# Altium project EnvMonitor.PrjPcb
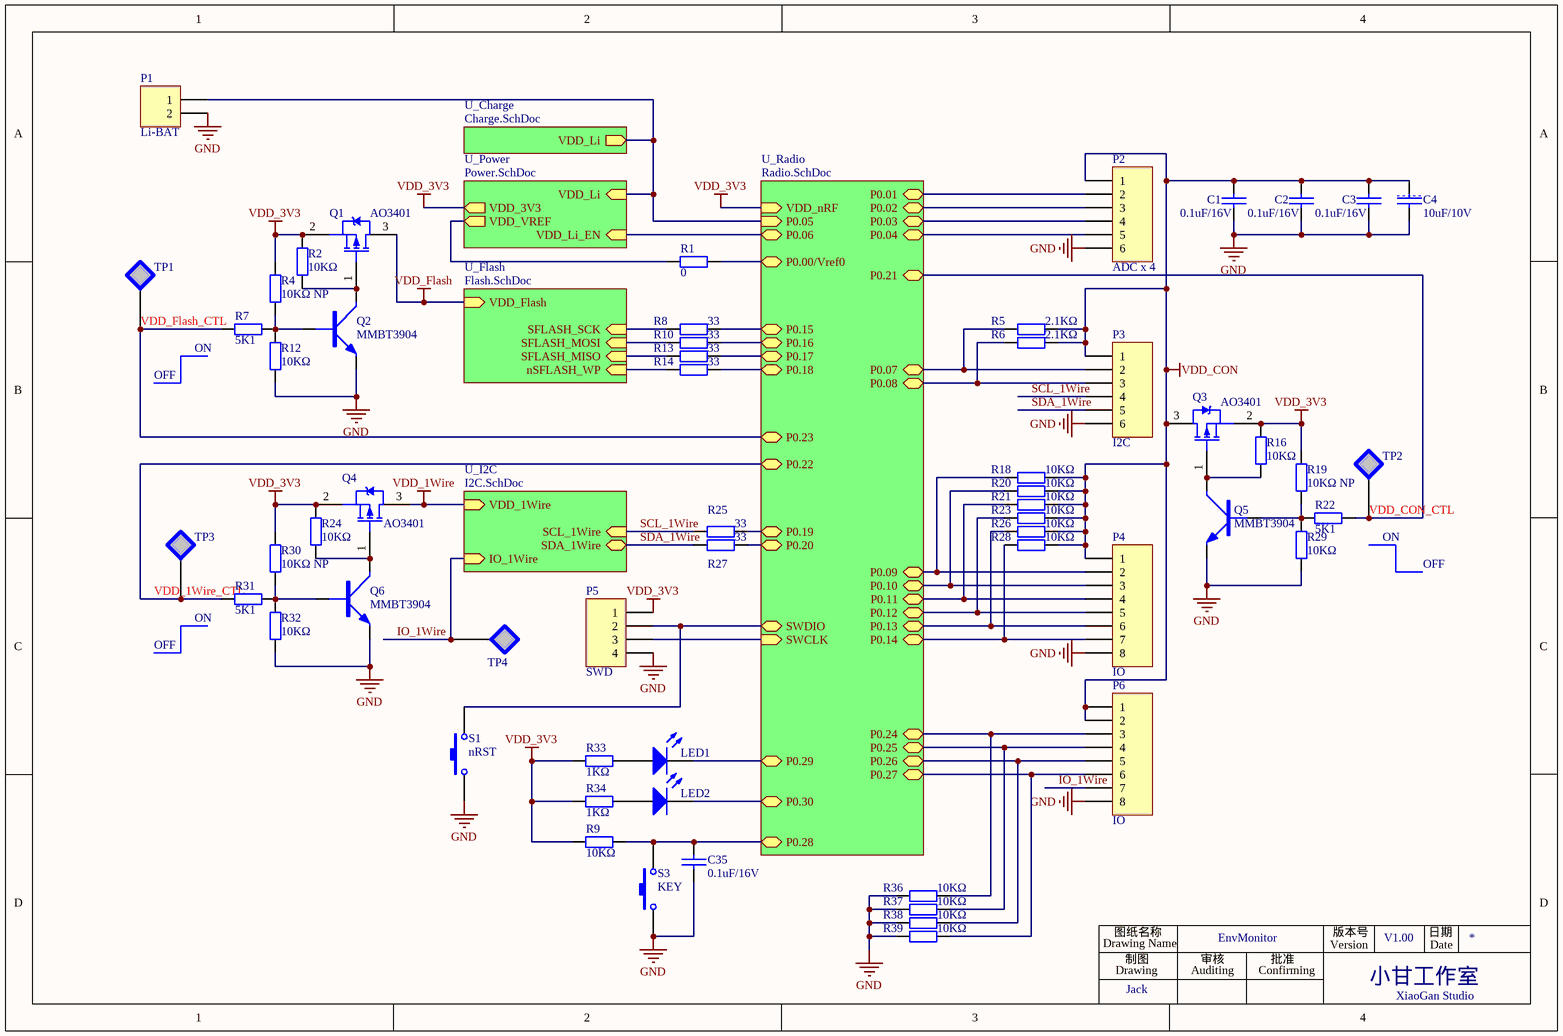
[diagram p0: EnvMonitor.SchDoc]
6 sheets, 146 parts. Net scope: hierarchical (ports join the sheet entries above them; power ports are global).
Sheets:
  EnvMonitor.SchDoc
    U_Radio = Radio.SchDoc
    U_Flash = Flash.SchDoc
    U_Power = Power.SchDoc
    U_I2C = I2C.SchDoc
    U_Charge = Charge.SchDoc

## Sheet EnvMonitor.SchDoc
size A4

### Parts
C1  0.1uF/16V  [0603]
C2  0.1uF/16V  [0603]
C3  0.1uF/16V  [0603]
C4  10uF/10V  [0805]
C35  0.1uF/16V  [0603]
LED1  LED_0603  [0603D]  (value not drawn)
LED2  LED_0603  [0603D]  (value not drawn)
P1  Li-BAT  [HDR1X2]
P2  ADC x 4  [HDR1X6]
P3  I2C  [HDR1X6]
P4  IO  [HDR1X8]
P5  SWD  [HDR1X4]
P6  IO  [HDR1X8]
Q1  AO3401  [SOT23]
Q2  MMBT3904  [SOT23]
Q3  AO3401  [SOT23]
Q4  AO3401  [SOT23]
Q5  MMBT3904  [SOT23]
Q6  MMBT3904  [SOT23]
R1  0  [0603]
R2  10KΩ  [0603]
R4  10KΩ NP  [0603]
R5  2.1KΩ  [0603]
R6  2.1KΩ  [0603]
R7  5K1  [0603]
R8  33  [0603]
R9  10KΩ  [0603]
R10  33  [0603]
R12  10KΩ  [0603]
R13  33  [0603]
R14  33  [0603]
R16  10KΩ  [0603]
R18  10KΩ  [0603]
R19  10KΩ NP  [0603]
R20  10KΩ  [0603]
R21  10KΩ  [0603]
R22  5K1  [0603]
R23  10KΩ  [0603]
R24  10KΩ  [0603]
R25  33  [0603]
R26  10KΩ  [0603]
R27  33  [0603]
R28  10KΩ  [0603]
R29  10KΩ  [0603]
R30  10KΩ NP  [0603]
R31  5K1  [0603]
R32  10KΩ  [0603]
R33  1KΩ  [0603]
R34  1KΩ  [0603]
R36  10KΩ  [0603]
R37  10KΩ  [0603]
R38  10KΩ  [0603]
R39  10KΩ  [0603]
S1  nRST  [SPST-2]
S3  KEY  [SPST-2]
TP1  (no value)  [TP-PAD1]  (no BOM)
TP2  (no value)  [TP-PAD1]  (no BOM)
TP3  (no value)  [TP-PAD1]  (no BOM)
TP4  (no value)  [TP-PAD1]  (no BOM)

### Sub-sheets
U_Charge = Charge.SchDoc: VDD_Li (out)
U_Flash = Flash.SchDoc: SFLASH_SCK (in), SFLASH_MOSI (in), SFLASH_MISO (in), nSFLASH_WP (in), VDD_Flash (in)
U_I2C = I2C.SchDoc: VDD_1Wire (in), IO_1Wire (in), SDA_1Wire (bidir), SCL_1Wire (in)
U_Power = Power.SchDoc: VDD_Li (in), VDD_3V3 (out), VDD_VREF (out), VDD_Li_EN (in)
U_Radio = Radio.SchDoc: SWDIO (bidir), SWCLK (in), P0.00/Vref0 (bidir), P0.01 (bidir), P0.02 (bidir), P0.03 (bidir), P0.04 (bidir), P0.05 (in), P0.06 (bidir), P0.07 (bidir), P0.08 (bidir), P0.09 (bidir), P0.10 (bidir), P0.11 (bidir), P0.12 (bidir), P0.13 (bidir), P0.14 (bidir), P0.15 (bidir), P0.16 (bidir), P0.17 (bidir), P0.18 (bidir), P0.19 (bidir), P0.20 (bidir), P0.21 (bidir), P0.22 (bidir), P0.23 (bidir), P0.24 (bidir), P0.25 (bidir), P0.26 (bidir), P0.27 (bidir), P0.28 (bidir), P0.29 (bidir), P0.30 (bidir), VDD_nRF (in)

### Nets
GND: C1.2 C2.2 C3.2 C4.2 C35.1 P1.2 P2.6 P3.6 P4.8 P5.4 P6.8 Q2.2 Q5.2 Q6.2 R12.1 R29.1 R32.1 R36.2 R37.2 R38.2 R39.2 S1.1 S3.1
VDD_1Wire: Q4.3(D) ; sheet U_I2C/VDD_1Wire
VDD_3V3: P5.1 Q1.2(S) Q3.2(S) Q4.2(S) R2.2 R4.2 R9.2 R16.2 R19.2 R24.2 R30.2 R33.2 R34.2 ; sheet U_Radio/VDD_nRF, sheet U_Power/VDD_3V3
VDD_CON: C1.1 C2.1 C3.1 C4.1 P2.1 P3.1 P4.1 P6.1 P6.2 Q3.3(D) R5.1 R6.1 R18.1 R20.1 R21.1 R23.1 R26.1 R28.1
VDD_Flash: Q1.3(D) ; sheet U_Flash/VDD_Flash
IO_1Wire: P6.7 TP4.1 ; sheet U_I2C/IO_1Wire
nSFLASH_WP: R14.2 ; sheet U_Flash/nSFLASH_WP
P0.00/Vref0: R1.1 ; sheet U_Radio/P0.00/Vref0
P0.01: P2.2 ; sheet U_Radio/P0.01
P0.02: P2.3 ; sheet U_Radio/P0.02
P0.03: P2.4 ; sheet U_Radio/P0.03
P0.04: P2.5 ; sheet U_Radio/P0.04
P0.05: P1.1 ; sheet U_Radio/P0.05, sheet U_Power/VDD_Li, sheet U_Charge/VDD_Li
P0.06: sheet U_Radio/P0.06, sheet U_Power/VDD_Li_EN
P0.07: P3.2 R5.2 ; sheet U_Radio/P0.07
P0.08: P3.3 R6.2 ; sheet U_Radio/P0.08
P0.09: P4.2 R18.2 ; sheet U_Radio/P0.09
P0.10: P4.3 R20.2 ; sheet U_Radio/P0.10
P0.11: P4.4 R21.2 ; sheet U_Radio/P0.11
P0.12: P4.5 R23.2 ; sheet U_Radio/P0.12
P0.13: P4.6 R26.2 ; sheet U_Radio/P0.13
P0.14: P4.7 R28.2 ; sheet U_Radio/P0.14
P0.15: R8.1 ; sheet U_Radio/P0.15
P0.16: R10.1 ; sheet U_Radio/P0.16
P0.17: R13.1 ; sheet U_Radio/P0.17
P0.18: R14.1 ; sheet U_Radio/P0.18
P0.19: R25.1 ; sheet U_Radio/P0.19
P0.20: R27.1 ; sheet U_Radio/P0.20
P0.24: P6.3 R36.1 ; sheet U_Radio/P0.24
P0.25: P6.4 R37.1 ; sheet U_Radio/P0.25
P0.26: P6.5 R38.1 ; sheet U_Radio/P0.26
P0.27: P6.6 R39.1 ; sheet U_Radio/P0.27
P0.28: C35.2 R9.1 S3.2 ; sheet U_Radio/P0.28
P0.29: LED1.2(K) ; sheet U_Radio/P0.29
P0.30: LED2.2(K) ; sheet U_Radio/P0.30
SCL_1Wire: P3.4 R25.2 ; sheet U_I2C/SCL_1Wire
SDA_1Wire: P3.5 R27.2 ; sheet U_I2C/SDA_1Wire
SFLASH_MISO: R13.2 ; sheet U_Flash/SFLASH_MISO
SFLASH_MOSI: R10.2 ; sheet U_Flash/SFLASH_MOSI
SFLASH_SCK: R8.2 ; sheet U_Flash/SFLASH_SCK
SWCLK: P5.3 ; sheet U_Radio/SWCLK
SWDIO: P5.2 S1.2 ; sheet U_Radio/SWDIO
VDD_1Wire_CTL: R31.2 TP3.1 ; sheet U_Radio/P0.22  [project net P0.22]
VDD_CON_CTL: R22.2 TP2.1 ; sheet U_Radio/P0.21  [project net P0.21]
VDD_Flash_CTL: R7.2 TP1.1 ; sheet U_Radio/P0.23  [project net P0.23]
VDD_VREF: R1.2 ; sheet U_Power/VDD_VREF
NetLED1_1: LED1.1(A) R33.1
NetLED2_1: LED2.1(A) R34.1
NetQ1_1: Q1.1(G) Q2.3 R2.1
NetQ2_1: Q2.1 R4.1 R7.1 R12.2
NetQ3_1: Q3.1(G) Q5.3 R16.1
NetQ4_1: Q4.1(G) Q6.3 R24.1
NetQ5_1: Q5.1 R19.1 R22.1 R29.2
NetQ6_1: Q6.1 R30.1 R31.1 R32.2

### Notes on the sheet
- OFF
- (near R7) ON
- (near R22) ON
- (near R31) ON

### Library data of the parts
C1-C4 C35 = CAP: 贴片陶瓷电容
LED1 LED2 = LED_0603: LED_0603 Typical RED, GREEN, YELLOW, AMBER GaAs LED
P1 = Header 2: Header, 2-Pin
P2 P3 = Header 6: Header, 6-Pin
P4 P6 = Header 8: Header, 8-Pin
P5 = Header 4: Header, 4-Pin
Q1 Q3 Q4 = DMP3098L: -30V,-3.8A   PMOS  70-120mΩ; Manufacturer: DIODES; Kind: 贴片MOS管; Remark: 关键元器件
Q2 Q5 Q6 = 9013: NPN三极管; Kind: 贴片三极管
R1 R2 R4-R10 R12-R14 R16 R18-R34 R36-R39 = RES_0603
S1 S3 = SW-PB: Switch
TP1-TP4 = TESTPOINT: Test Point

## Sheet Radio.SchDoc: PCA100024 - Radio
size A4; Revision: 1.0.0; SheetNumber: 1; SheetTotal: 3; DrawnBy: RUBR; ProjectNumber: 4400; PCBRevision: 0141RUBR; DocumentSize: A4; PCAName: PCA10024; PCBNumber: 400081
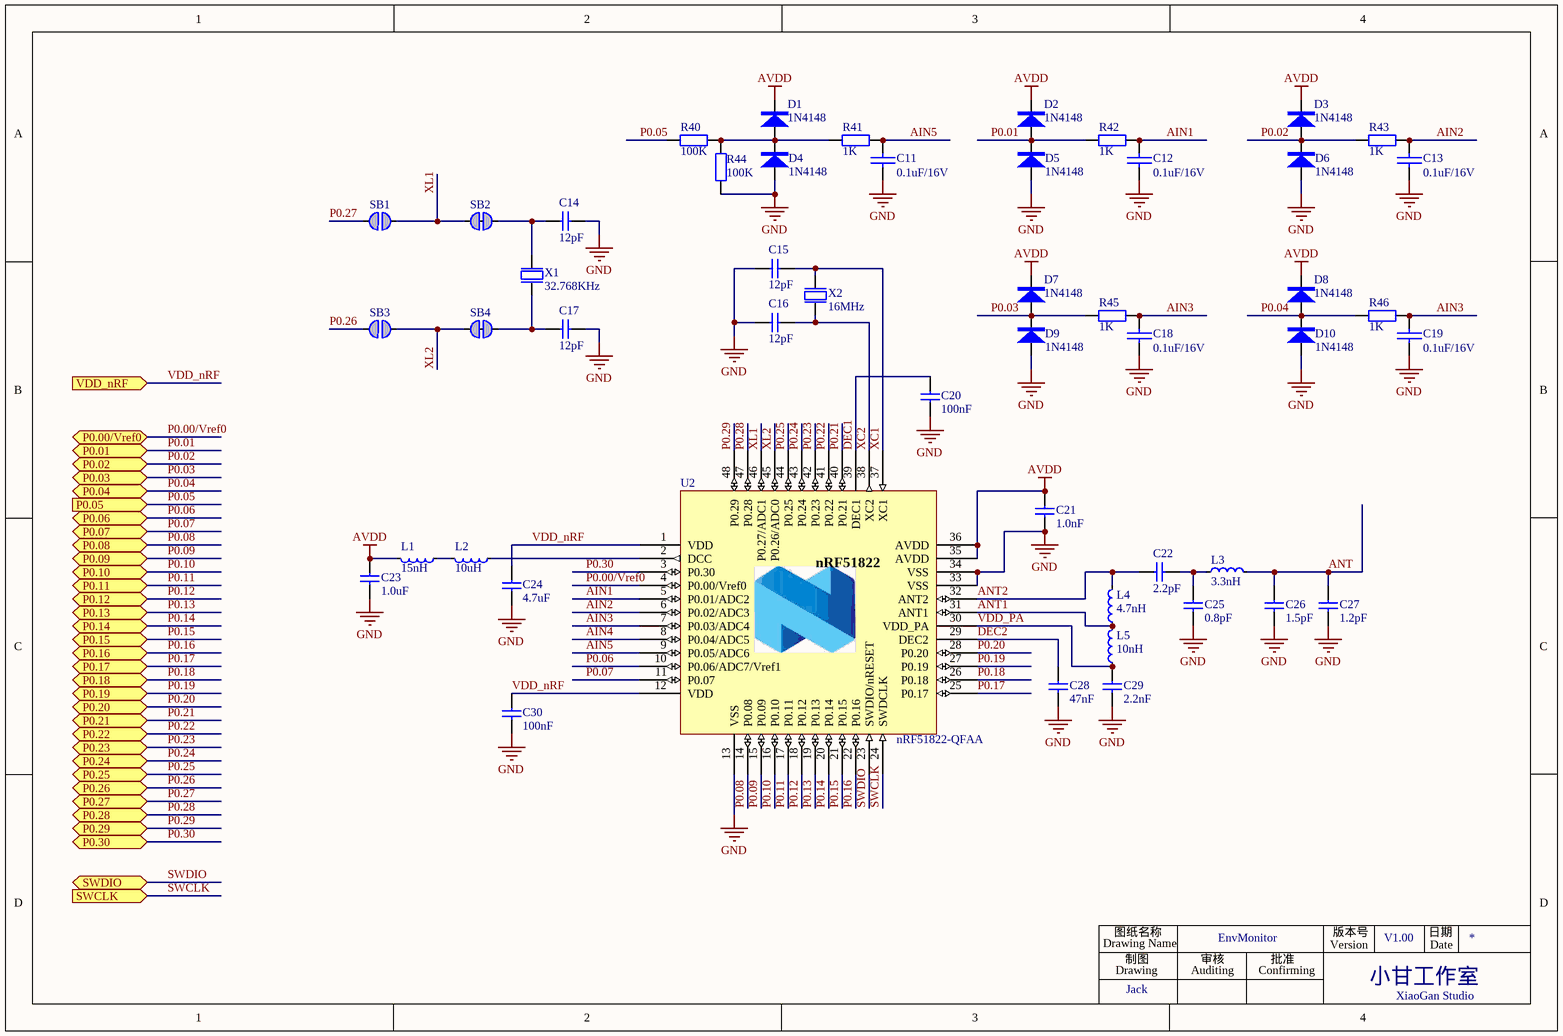
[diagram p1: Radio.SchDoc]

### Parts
C11  0.1uF/16V  [0603]
C12  0.1uF/16V  [0603]
C13  0.1uF/16V  [0603]
C14  12pF  [0603]
C15  12pF  [0603]
C16  12pF  [0603]
C17  12pF  [0603]
C18  0.1uF/16V  [0603]
C19  0.1uF/16V  [0603]
C20  100nF  [0603]
C21  1.0nF  [0603]
C22  2.2pF  [0603]
C23  1.0uF  [0603]
C24  4.7uF  [0603]
C25  0.8pF  [0603]
C26  1.5pF  [0603]
C27  1.2pF  [0603]
C28  47nF  [0603]
C29  2.2nF  [0603]
C30  100nF  [0603]
D1  1N4148  [SMA]
D2  1N4148  [SMA]
D3  1N4148  [SMA]
D4  1N4148  [SMA]
D5  1N4148  [SMA]
D6  1N4148  [SMA]
D7  1N4148  [SMA]
D8  1N4148  [SMA]
D9  1N4148  [SMA]
D10  1N4148  [SMA]
L1  15nH  [0603]
L2  10uH  [0603]
L3  3.3nH  [0603]
L4  4.7nH  [0603]
L5  10nH  [0603]
R40  100K  [0603]
R41  1K  [0603]
R42  1K  [0603]
R43  1K  [0603]
R44  100K  [0603]
R45  1K  [0603]
R46  1K  [0603]
SB1  Solderbridge  [Solderbridge]  (value not drawn)  (no BOM)
SB2  Solderbridge  [Solderbridge_Shorted]  (value not drawn)  (net tie, no BOM)
SB3  Solderbridge  [Solderbridge]  (value not drawn)  (no BOM)
SB4  Solderbridge  [Solderbridge_Shorted]  (value not drawn)  (net tie, no BOM)
U2  nRF51822-QFAA  [QFN40P600X600X90-48N]
X1  32.768KHz  [FC-135]
X2  16MHz  [BT-XTAL_2520]

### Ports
P0.00/Vref0 (bidir), P0.01 (bidir), P0.02 (bidir), P0.03 (bidir), P0.04 (bidir), P0.05 (in), P0.06 (bidir), P0.07 (bidir), P0.08 (bidir), P0.09 (bidir), P0.10 (bidir), P0.11 (bidir), P0.12 (bidir), P0.13 (bidir), P0.14 (bidir), P0.15 (bidir), P0.16 (bidir), P0.17 (bidir), P0.18 (bidir), P0.19 (bidir), P0.20 (bidir), P0.21 (bidir), P0.22 (bidir), P0.23 (bidir), P0.24 (bidir), P0.25 (bidir), P0.26 (bidir), P0.27 (bidir), P0.28 (bidir), P0.29 (bidir), P0.30 (bidir), SWCLK (in), SWDIO (bidir), VDD_nRF (in)

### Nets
AVDD: C21.1 C23.2 D1.2 D2.2 D3.2 D7.2 D8.2 L1.2 U2.35(AVDD) U2.36(AVDD)
GND: C11.2(P2) C12.2(P2) C13.2(P2) C14.2 C15.2 C16.2 C17.2 C18.2(P2) C19.2(P2) C20.2 C21.2 C23.1 C24.2 C25.2 C26.2 C27.2 C28.2 C29.2 C30.2 D4.1 D5.1 D6.1 D9.1 D10.1 R44.1 U2.13(VSS) U2.33(VSS) U2.34(VSS) U2.49 X2.2(GND) X2.4(GND)
VDD_nRF: C24.1 C30.1 U2.1(VDD) U2.12(VDD) ; port VDD_nRF  [project net VDD_3V3]
AIN1: C12.1(P1) R42.2 U2.5(P0.01/ADC2)
AIN2: C13.1(P1) R43.2 U2.6(P0.02/ADC3)
AIN3: C18.1(P1) C19.1(P1) R45.2 R46.2 U2.7(P0.03/ADC4)
AIN4: U2.8(P0.04/ADC5)
AIN5: C11.1(P1) R41.2 U2.9(P0.05/ADC6)
ANT: C26.1 C27.1 L3.2
ANT1: L4.1 L5.2 U2.31(ANT1)
ANT2: C22.1 L4.2 U2.32(ANT2)
DEC1: C20.1 U2.39(DEC1)
DEC2: C28.1 U2.29(DEC2)
P0.00/Vref0: U2.4(P0.00/Vref0) ; port P0.00/Vref0
P0.01: D2.1 D5.2 R42.1 ; port P0.01
P0.02: D3.1 D6.2 R43.1 ; port P0.02
P0.03: D7.1 D9.2 R45.1 ; port P0.03
P0.04: D8.1 D10.2 R46.1 ; port P0.04
P0.05: R40.2 ; port P0.05
P0.06: U2.10(P0.06/ADC7/Vref1) ; port P0.06
P0.07: U2.11(P0.07) ; port P0.07
P0.08: U2.14(P0.08) ; port P0.08
P0.09: U2.15(P0.09) ; port P0.09
P0.10: U2.16(P0.10) ; port P0.10
P0.11: U2.17(P0.11) ; port P0.11
P0.12: U2.18(P0.12) ; port P0.12
P0.13: U2.19(P0.13) ; port P0.13
P0.14: U2.20(P0.14) ; port P0.14
P0.15: U2.21(P0.15) ; port P0.15
P0.16: U2.22(P0.16) ; port P0.16
P0.17: U2.25(P0.17) ; port P0.17
P0.18: U2.26(P0.18) ; port P0.18
P0.19: U2.27(P0.19) ; port P0.19
P0.20: U2.28(P0.20) ; port P0.20
P0.21: U2.40(P0.21) ; port P0.21
P0.22: U2.41(P0.22) ; port P0.22
P0.23: U2.42(P0.23) ; port P0.23
P0.24: U2.43(P0.24) ; port P0.24
P0.25: U2.44(P0.25) ; port P0.25
P0.26: SB3.2 ; port P0.26
P0.27: SB1.2 ; port P0.27
P0.28: U2.47(P0.28) ; port P0.28
P0.29: U2.48(P0.29) ; port P0.29
P0.30: U2.3(P0.30) ; port P0.30
SWCLK: U2.24(SWDCLK) ; port SWCLK
SWDIO: U2.23(SWDIO/nRESET) ; port SWDIO
VDD_PA: C29.1 L5.1 U2.30(VDD_PA)
XC1: C15.1 U2.37(XC1) X2.1(inp)
XC2: C16.1 U2.38(XC2) X2.3(out)
XL1: SB1.1 SB2.2 U2.46(P0.27/ADC1)
XL2: SB3.1 SB4.2 U2.45(P0.26/ADC0)
NetC14_1: C14.1 SB2.1 X1.2(out)
NetC17_1: C17.1 SB4.1 X1.1(inp)
NetC22_2: C22.2 C25.1 L3.1
NetD1_1: D1.1 D4.2 R40.1 R41.1 R44.2
NetL1_1: L1.1 L2.2
NetL2_1: L2.1 U2.2(DCC)

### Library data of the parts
C11-C13 C18 C19 = CAP: 贴片陶瓷电容
C14-C17 = C0402-12p: Capacitor, NP0, ?%; Note: 50V; Artikkelnr Noca: 20029159
C20 C30 = C0402-100n: Capacitor, X7R, ?0%; Note: 16V; Artikkelnr Noca: 20039200
C21 = C0402-1n0: Capacitor, X7R, ?0%; Note: 50V; Artikkelnr Noca: 20039223
C22 = C0402-2.2p: Capacitor, NP0, ?.1pF; Note: 50V; Artikkelnr Noca: 20029145
C23 = C0603-1?: Capacitor, X7R, ?0%; Value: 1.0µF; Note: 16V; Artikkelnr Noca: 20039335
C24 = C0603-4?: Capacitor, X5R, ?0%; Value: 4.7µF; Note: 6.3V; Artikkelnr Noca: 20069060
C25 = C0402-0.8p: Capacitor, NP0, ?%; Note: 50V; Artikkelnr Noca: 20029147
C26 = C0402-1.5p: Capacitor, NP0, ?.1pF; Note: 50V; Artikkelnr Noca: 20029139
C27 = C0402-1.2p: Capacitor, NP0, ?.1pF; Note: 50V; Artikkelnr Noca: 20029157
C28 = C0402-47n: Capacitor, X7R, ?0%; Note: Chip Cap 10%; Artikkelnr Noca: 20039389
C29 = C0402-2n2: Capacitor, X7R, ?0%; Note: 50V; Artikkelnr Noca: 20039221
D1-D10 = DIODE: 贴片二极管; Remark: 可用1N5819替代
L1 = L0402-15n: Inductor, 320mA, ?%; Manufacturer: Taiyo Yuden; Manufacturer Part Number: HK100515NJ-T; 2nd source part number: 658-1328; Note: High frequency chip inductor ?0%; Artikkelnr Noca: 33029323
L2 = L0603-10?: Inductor, 80mA, ?0%; Part Number: L0603-10祹ISHIDDEN=T; Manufacturer: Taiyo Yuden; Manufacturer Part Number: LBMF1608T100K; 2nd source part number: 178-6105; Value: 10µH; Note: LBMF1608T100K 10µH 80mA 0603; Artikkelnr Noca: 33029314
L3 = L0402-3n3: Inductor, 190mA, ?.1nH; Manufacturer: Murata; Manufacturer Part Number: LQP15MN3N3B02D; Note: High frequency chip inductor ?%; Artikkelnr Noca: 33029369
L4 = L0402-4n7: Inductor, 160mA, ?.1nH; Manufacturer: Murata; Manufacturer Part Number: LQP15MN4N7B02D; Note: High frequency chip inductor ?%; Artikkelnr Noca: 33029164
L5 = L0402-10n: Inductor, 100mA, ?%; Manufacturer: Murata; Manufacturer Part Number: LQP15MN10NG02D; Note: High frequency chip inductor ?%; Artikkelnr Noca: 33029425
R40-R46 = RES_0603
SB1 SB3 = Solderbridge: Artikkelnr Noca: N.A.
SB2 SB4 = Solderbridge Shorted: Shorted Solderbridge; Artikkelnr Noca: N.A.
U2 = nRF51822_QFAA: Multi-protocol Bluetooth Low Energy and 2.4GHz proprietary system-on-chip; Part Number: nRF51822-QFAA-XLR2.4; Manufacturer: Nordic Semiconductor; Manufacturer Part Number: nRF51822-QFAAGx; Note: nRF51822 - QFN48 6x6 0.4mm pitch; Artikkelnr Noca: 15079242
X1 = XTAL_FC-135 32.768k: EPSON TOYOCOM - FC-135 32.768KHZ ?0PPM,9.0PF - CRYSTAL, SM, WATCH; 2nd source part number: 127-8037; Note: XTAL SMD 32.768kHz, 3215; Artikkelnr Noca: 22019091
X2 = NX2520SA-16MHZ-STD-CSW-5: XTAL SMD 2520, 16MHz, 8pF, ?5ppm; Manufacturer: NDK; Note: XTAL SMD 16.000MHz; Artikkelnr Noca: 22019192

## Sheet Flash.SchDoc
size A4
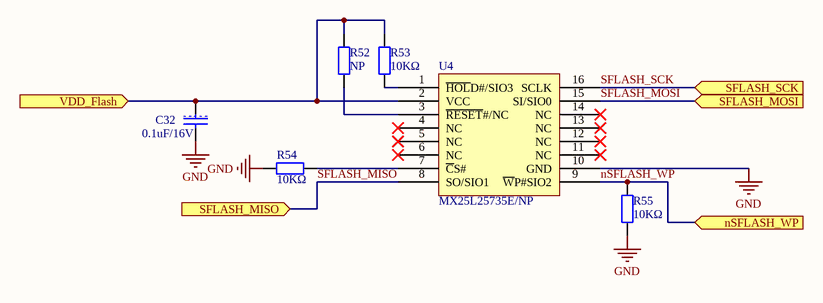
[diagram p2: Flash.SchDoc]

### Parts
C32  0.1uF/16V  [0603]  (no BOM)
R52  NP  [0603]
R53  10KΩ  [0603]
R54  10KΩ  [0603]
R55  10KΩ  [0603]
U4  MX25L25735E/NP  [SOIC16W]  (no BOM)

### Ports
nSFLASH_WP (in), SFLASH_MISO (in), SFLASH_MOSI (in), SFLASH_SCK (in), VDD_Flash (in)

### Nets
GND: C32.2 R54.2 R55.2 U4.10(GND)
VDD_Flash: C32.1 R52.2 R53.2 U4.2(VCC) ; port VDD_Flash
nSFLASH_WP: R55.1 U4.9(~{W}P#SIO2) ; port nSFLASH_WP
SFLASH_MISO: U4.8(SO/SIO1) ; port SFLASH_MISO
SFLASH_MOSI: U4.15(SI/SIO0) ; port SFLASH_MOSI
SFLASH_SCK: U4.16(SCLK) ; port SFLASH_SCK
NetR52_1: R52.1 U4.3(~{RESET}#/NC)
NetR53_1: R53.1 U4.1(~{HOL}D#/SIO3)
NetR54_1: R54.1 U4.7(~{C}S#)

Not connected (* = marked no-connect by the designer): U4 4(NC)* 5(NC)* 6(NC)* 11(NC)* 12(NC)* 13(NC)* 14(NC)*

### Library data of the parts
C32 = CAP: 贴片陶瓷电容
R52-R55 = RES_0603
U4 = MX25L25735E: SPI_flash; Manufacturer: MXIC; Kind: 集成电路; Remark: 关键元器件; 规格: 16-PIN SOP(300mil)

## Sheet Power.SchDoc
size A4
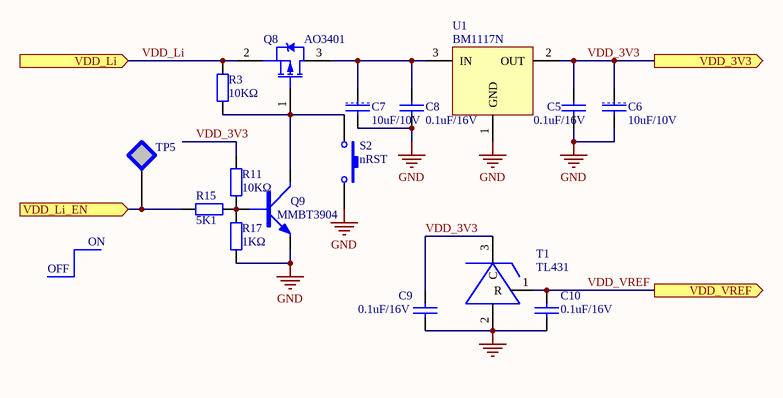
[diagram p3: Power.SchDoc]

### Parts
C5  0.1uF/16V  [0603]
C6  10uF/10V  [0805]
C7  10uF/10V  [0805]
C8  0.1uF/16V  [0603]
C9  0.1uF/16V  [0603]
C10  0.1uF/16V  [0603]
Q8  AO3401  [SOT23]
Q9  MMBT3904  [SOT23]
R3  10KΩ  [0603]
R11  10KΩ  [0603]
R15  5K1  [0603]
R17  1KΩ  [0603]
S2  nRST  [SPST-2]
T1  TL431  [TL-431]
TP5  (no value)  [TP-PAD1]  (no BOM)
U1  BM1117N  [TO-252]

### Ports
VDD_3V3 (out), VDD_Li (in), VDD_Li_EN (in), VDD_VREF (out)

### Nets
GND: C5.2 C6.2 C7.2 C8.2 C9.2 C10.2 Q9.2 R17.1 S2.1 T1.2 U1.1(GND)
VDD_3V3: C5.1 C6.1 C9.1 R11.2 T1.3(C) U1.2(OUT) ; port VDD_3V3
P0.06: R15.2 TP5.1 ; port VDD_Li_EN
VDD_Li: Q8.2(S) R3.2 ; port VDD_Li  [project net P0.05]
VDD_VREF: C10.1 T1.1(R) ; port VDD_VREF
NetC7_1: C7.1 C8.1 Q8.3(D) U1.3(IN)
NetQ8_1: Q8.1(G) Q9.3 R3.1 S2.2
NetQ9_1: Q9.1 R11.1 R15.1 R17.2

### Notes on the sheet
- OFF
- ON

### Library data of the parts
C5-C10 = CAP: 贴片陶瓷电容
Q8 = DMP3098L: as Q1 on sheet EnvMonitor
Q9 = 9013: NPN三极管; Kind: 贴片三极管
R3 R11 R15 R17 = RES_0603
S2 = SW-PB: Switch
TP5 = TESTPOINT: Test Point
U1 = AZ1084

## Sheet I2C.SchDoc
size A4
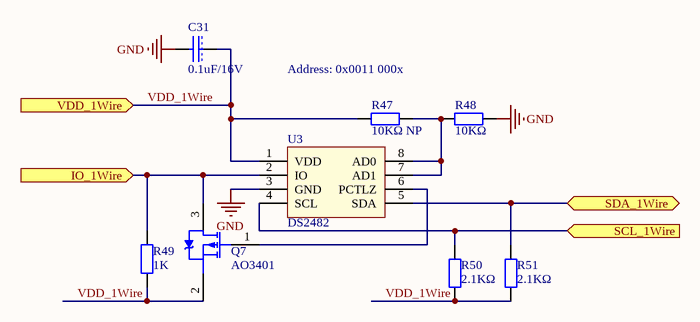
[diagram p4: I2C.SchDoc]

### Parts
C31  0.1uF/16V  [0603]  (no BOM)
Q7  AO3401  [SOT23]
R47  10KΩ NP  [0603]
R48  10KΩ  [0603]
R49  1K  [0603]
R50  2.1KΩ  [0603]
R51  2.1KΩ  [0603]
U3  DS2482

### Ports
IO_1Wire (in), SCL_1Wire (in), SDA_1Wire (bidir), VDD_1Wire (in)

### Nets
GND: C31.2 R48.1 U3.3(GND)
VDD_1Wire: C31.1 Q7.2(S) R47.2 R49.1 R50.2 R51.2 U3.1(VDD) ; port VDD_1Wire
IO_1Wire: Q7.3(D) R49.2 U3.2(IO) ; port IO_1Wire
SCL_1Wire: R50.1 U3.4(SCL) ; port SCL_1Wire
SDA_1Wire: R51.1 U3.5(SDA) ; port SDA_1Wire
NetQ7_1: Q7.1(G) U3.6(PCTLZ)
NetR47_1: R47.1 R48.2 U3.7(AD1) U3.8(AD0)

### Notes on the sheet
- Address: 0x0011 000x

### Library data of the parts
C31 = CAP: 贴片陶瓷电容
Q7 = DMP3098L: as Q1 on sheet EnvMonitor
R47-R51 = RES_0603

## Sheet Charge.SchDoc
size A4
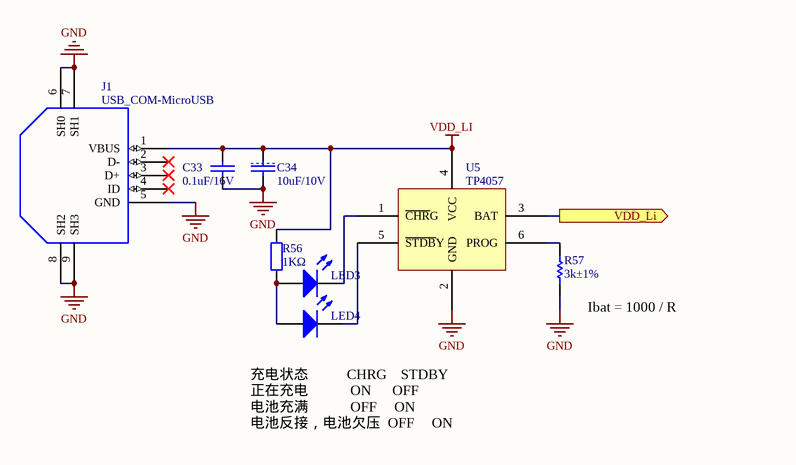
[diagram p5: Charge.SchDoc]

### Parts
C33  0.1uF/16V  [0603]
C34  10uF/10V  [0805]
J1  USB_COM-MicroUSB  [USB_MINIB_SMT]
LED3  LED_0603  [0603D]  (value not drawn)
LED4  LED_0603  [0603D]  (value not drawn)
R56  1KΩ  [0603]
R57  3k±1%  [0603]
U5  TP4057  [SOT23-6]

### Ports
VDD_Li (out)

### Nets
GND: C33.2 C34.2 J1.5(GND) J1.6(SH0) J1.7(SH1) J1.8(SH2) J1.9(SH3) R57.1 U5.2(GND)
VDD_LI: C33.1 C34.1 J1.1(VBUS) R56.1 U5.4(VCC)
P0.05: U5.3(BAT) ; port VDD_Li
NetLED3_1: LED3.1(A) LED4.1(A) R56.2
NetLED3_2: LED3.2(K) U5.1(~{CHR}G)
NetLED4_2: LED4.2(K) U5.5(~{STDB}Y)
NetR57_2: R57.2 U5.6(PROG)

Not connected (* = marked no-connect by the designer): J1 2(D-)* 3(D+)* 4(ID)*

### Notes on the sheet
- (near R57) Ibat = 1000 / R
- (near LED4) 充电状态           CHRG    STDBY
  正在充电            ON      OFF
  电池充满            OFF     ON
  电池反接，电池欠压  OFF     ON

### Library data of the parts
C33 C34 = CAP: 贴片陶瓷电容
J1 = USB_COM-MiniUSB: Text Field1: 100; Text Field2: 80
LED3 LED4 = LED_0603: as LED1 on sheet EnvMonitor
R56 = RES_0603
R57 = Res1: 贴片电阻
U5 = TP4057: 锂电充电芯片; Manufacturer: 南京拓微集成电路; Kind: 集成电路; Remark: 关键元器件

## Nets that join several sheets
GND: EnvMonitor (23 pins), Radio (31 pins), Flash (C32.2 R54.2 R55.2 U4.10), Power (11 pins), I2C (C31.2 R48.1 U3.3), Charge (9 pins)
VDD_1Wire: EnvMonitor (Q4.3), I2C (7 pins)
VDD_3V3: EnvMonitor (13 pins), Radio (C24.1 C30.1 U2.1 U2.12), Power (6 pins)
VDD_Flash: EnvMonitor (Q1.3), Flash (C32.1 R52.2 R53.2 U4.2)
IO_1Wire: EnvMonitor (P6.7 TP4.1), I2C (Q7.3 R49.2 U3.2)
nSFLASH_WP: EnvMonitor (R14.2), Flash (R55.1 U4.9)
P0.00/Vref0: EnvMonitor (R1.1), Radio (U2.4)
P0.01: EnvMonitor (P2.2), Radio (D2.1 D5.2 R42.1)
P0.02: EnvMonitor (P2.3), Radio (D3.1 D6.2 R43.1)
P0.03: EnvMonitor (P2.4), Radio (D7.1 D9.2 R45.1)
P0.04: EnvMonitor (P2.5), Radio (D8.1 D10.2 R46.1)
P0.05: EnvMonitor (P1.1), Radio (R40.2), Power (Q8.2 R3.2), Charge (U5.3)
P0.06: Radio (U2.10), Power (R15.2 TP5.1)
P0.07: EnvMonitor (P3.2 R5.2), Radio (U2.11)
P0.08: EnvMonitor (P3.3 R6.2), Radio (U2.14)
P0.09: EnvMonitor (P4.2 R18.2), Radio (U2.15)
P0.10: EnvMonitor (P4.3 R20.2), Radio (U2.16)
P0.11: EnvMonitor (P4.4 R21.2), Radio (U2.17)
P0.12: EnvMonitor (P4.5 R23.2), Radio (U2.18)
P0.13: EnvMonitor (P4.6 R26.2), Radio (U2.19)
P0.14: EnvMonitor (P4.7 R28.2), Radio (U2.20)
P0.15: EnvMonitor (R8.1), Radio (U2.21)
P0.16: EnvMonitor (R10.1), Radio (U2.22)
P0.17: EnvMonitor (R13.1), Radio (U2.25)
P0.18: EnvMonitor (R14.1), Radio (U2.26)
P0.19: EnvMonitor (R25.1), Radio (U2.27)
P0.20: EnvMonitor (R27.1), Radio (U2.28)
P0.21: EnvMonitor (R22.2 TP2.1), Radio (U2.40)
P0.22: EnvMonitor (R31.2 TP3.1), Radio (U2.41)
P0.23: EnvMonitor (R7.2 TP1.1), Radio (U2.42)
P0.24: EnvMonitor (P6.3 R36.1), Radio (U2.43)
P0.25: EnvMonitor (P6.4 R37.1), Radio (U2.44)
P0.26: EnvMonitor (P6.5 R38.1), Radio (SB3.2)
P0.27: EnvMonitor (P6.6 R39.1), Radio (SB1.2)
P0.28: EnvMonitor (C35.2 R9.1 S3.2), Radio (U2.47)
P0.29: EnvMonitor (LED1.2), Radio (U2.48)
P0.30: EnvMonitor (LED2.2), Radio (U2.3)
SCL_1Wire: EnvMonitor (P3.4 R25.2), I2C (R50.1 U3.4)
SDA_1Wire: EnvMonitor (P3.5 R27.2), I2C (R51.1 U3.5)
SFLASH_MISO: EnvMonitor (R13.2), Flash (U4.8)
SFLASH_MOSI: EnvMonitor (R10.2), Flash (U4.15)
SFLASH_SCK: EnvMonitor (R8.2), Flash (U4.16)
SWCLK: EnvMonitor (P5.3), Radio (U2.24)
SWDIO: EnvMonitor (P5.2 S1.2), Radio (U2.23)
VDD_VREF: EnvMonitor (R1.2), Power (C10.1 T1.1)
